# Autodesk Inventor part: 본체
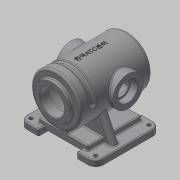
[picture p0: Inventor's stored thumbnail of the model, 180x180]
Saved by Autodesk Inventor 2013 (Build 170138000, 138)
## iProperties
Created: 2015-10
Part Number: 본체
Document SubType Name: Modeling
Designer: mdu
Density: 2.71 g/cm^3
Material: 일반
Mass: 4592.12 g
Surface Area: 2715.66 cm^2
Volume: 1694.51 cm^3
Author: mdu
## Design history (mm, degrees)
sketch "스케치1"
  geometry: L1 (-100, 85)-(-50, 85); L2 (-50, 85)-(-50, -85); L3 (-50, -85)-(-100, -85); L4 (-100, -85)-(-100, 85); L5 (50, 85)-(100, 85); L6 (100, 85)-(100, -85); L7 (100, -85)-(50, -85); L8 (50, -85)-(50, 85); 3 further points
  constraints: 16 end point, 4 parallel, 2 equal length, 2 horizontal, 2 horizontal alignment, 2 midpoint, 2 perpendicular
  dimensions: "d0" = 100 distance between parallel lines of L8 L2; "d1" = 170 distance of L3.end L1.start; "d3" = 200 distance between parallel lines of L6 L4; "d4" = 50 distance from line of point (0, 0) L2 (= 0.5 x d0)
extrude "돌출1" new body sketch "스케치1" distance "d5" = 16; taper "d6" = 0 deg
node "작업 평면1"
sketch "스케치2"
  geometry: L1 (-65, 70)-(65, 70); L2 (65, 70)-(65, -70); L3 (65, -70)-(-65, -70); L4 (-65, -70)-(-65, 70); 3 further points
  constraints: 8 end point, 2 midpoint, 2 parallel, 1 horizontal, 1 horizontal alignment, 1 perpendicular, 1 vertical alignment
  dimensions: "d8" = 130 distance of L2.end L3.end; "d9" = 140 distance of L1.end L2.end
extrude "돌출2" join sketch "스케치2" distance "d10" = 20; taper "d11" = 0 deg
sketch "스케치3"
  geometry: L1 (-100, 110)-(100, 110); L2 (85, 0)-(-85, 0) reference; L3 (100, 110)-(100, 175); L4 (100, 175)-(-90, 175); L5 (-90, 175)-(-90, 156); L6 (-90, 156)-(-100, 156); L7 (-100, 156)-(-100, 110); L8 (90, 110)-(90, 165); L9 (90, 165)-(-75, 165); L10 (-75, 165)-(-75, 110); L11 (-100, 142.5)-(-75, 142.5); 3 further points
  constraints: 20 end point, 5 perpendicular, 4 parallel, 4 point on line, 2 midpoint, 1 horizontal, 1 vertical alignment
  dimensions: "d12" = 110 distance from line of L2 L1.end; "d13" = 200 distance of L1.start L1.end; "d14" = 130 diameter of L4 L1; "d15" = 92 diameter of L6 L1; "d16" = 10 distance of L5.end L6.end; "d42" = 110 diameter of L9 L1; "d43" = 10 distance between parallel lines of L3 L8; "d44" = 25 distance between parallel lines of L10 L7; "d45" = 65 diameter of L11 L1
revolve "회전1" sketch "스케치3" stored, may be unused: angle "d17" = 90 deg
sketch "스케치4"
  geometry: L1 (-50, 70)-(50, 70) reference; L2 (50, -70)-(-50, -70) reference; L3 (-10, 70)-(-10, -70); L4 (10, -70)-(10, 70); 1 further point
  constraints: 4 end point, 4 point on line, 2 perpendicular
  dimensions: "d18" = 20 distance between parallel lines of L4 L3; "d19" = 10 distance from line of point (0, 0) L3
extrude "돌출3" join sketch "스케치4" stored distance "d20" = 10; taper "d21" = 0 deg
node "작업 평면2"
sketch "스케치5"
  geometry: L1 (-50, -8)-(0, -8) reference; L2 (100, -8)-(150, -8) reference; L3 (-40, -8)-(-8.943, -74.601); L4 (140, -8)-(108.943, -74.601); L5 (-50, 8)-(-50, -8) reference; L6 (150, 8)-(150, -8) reference; A1 r 65 centre (50, -102) between (-8.943, -74.601) and (108.943, -74.601) reference; 1 further point
  constraints: 4 end point, 2 point on circle, 2 point on line, 1 equal length
  dimensions: "d23" = 10 distance from line of L3.start L5; "d24" = 10 distance from line of L4.start L6; "d25" = 25 deg angle of L3 L5
feature "리브1" sketch "스케치5" dims "d26" = 1, "d27" = 20, "d28" = 0
node "작업 평면3"
sketch "스케치6"
  geometry: L1 (100, 156)-(100, 64) reference; C1 r 40 at (-25, 110); 2 further points
  constraints: 1 centre point, 1 horizontal alignment, 1 midpoint
  dimensions: "d37" = 80 diameter of C1; "d38" = 125 distance from line of C1.centre L1
extrude "돌출4" join sketch "스케치6" stored distance "d39" = 10; taper "d40" = 0 deg
hole "구멍1" diameter "d48" = 42; stored, may be unused: countersink angle "d52" = 90 deg, drill point angle "d54" = 118 deg; dims "d46" = 10, "d47" = 10, "d49" = 6, "d50" = 52, "d51" = 18, "d53" = 8
sketch "스케치7"
  geometry: C1 r 40 at (0, 0) reference; 2 further points
  constraints: 1 horizontal alignment
  dimensions: "d55" = 32.5 distance of point (32.5, 0) C1.centre
hole "구멍2" sketch "스케치7" at (32.5, 0) diameter "d56" = 3.242; stored, may be unused: countersink angle "d60" = 90 deg, drill point angle "d62" = 118 deg; dims "d57" = 11, "d58" = 52, "d59" = 18, "d61" = 13
sketch "스케치8"
  geometry: C1 r 46 at (0, 0) reference; 2 further points
  constraints: 1 vertical alignment
  dimensions: "d66" = 39 distance of C1.centre point (0, 39)
hole "구멍3" sketch "스케치8" at (0, 39) diameter "d67" = 3.242; stored, may be unused: countersink angle "d71" = 90 deg, drill point angle "d73" = 118 deg; dims "d68" = 11, "d69" = 52, "d70" = 18, "d72" = 13
fillet "모깎기7" dims "d77" = 20, "d78" = 5, "d79" = 3, "d80" = 10, "d107" = 10
fillet "모깎기8" dims "d81" = 3
fillet "모깎기9" dims "d82" = 3
fillet "모깎기10" dims "d83" = 3, "d84" = 0.3
chamfer "모따기1" distance "d85" = 1; stored, may be unused: second distance "d86" = 2, angle "d87" = 45 deg
node "작업 평면4"
sketch "스케치10"
  geometry: 5 further points
  constraints: 2 horizontal alignment, 2 vertical alignment
  dimensions: "d90" = 170 distance of point (85, 70) point (-85, 70); "d91" = 140 distance of point (-85, 70) point (-85, -70); "d92" = 70 vertical distance of point (0, 0) point (-85, -70) (= 0.5 x d91); "d93" = 85 horizontal distance of point (0, 0) point (-85, 70) (= 0.5 x d90)
hole "구멍4" sketch "스케치10" at (-85, 70), (85, 70), (85, -70), (-85, -70) diameter "d94" = 10; stored, may be unused: countersink angle "d98" = 90 deg, drill point angle "d100" = 118 deg; dims "d95" = 6, "d96" = 4, "d97" = 2, "d99" = 8
node "작업 평면5"
sketch "스케치12" dims "d22" = -90
  geometry: L1 (-65, -90)-(65, -90) reference; L2 (65, 85)-(-65, 85) reference; L3 (0, -90)-(0, 85); 3 further points
  constraints: 3 midpoint, 2 end point, 1 coincident, 1 other
feature "엠보싱3" sketch "스케치12" dims "d105" = 1, "d106" = 0
node "작업축1"
sketch "스케치13"
  geometry: L1 (-85, 175)-(90, 175) reference; L2 (-65, 175)-(-50, 175); L3 (-50, 175)-(-50, 170); L4 (-50, 170)-(-65, 170); L5 (-65, 170)-(-65, 175); L6 (-90, 50)-(-90, 170) reference; L7 (-140, 110)-(140, 110) reference; 1 further point
  constraints: 8 end point, 2 parallel, 1 horizontal, 1 perpendicular, 1 point on line
  dimensions: "d108" = 25 distance between parallel lines of L5 L6; "d109" = 15 distance of L3.end L4.end; "d110" = 5 distance of L2.end L3.end
revolve "회전2" sketch "스케치13" stored, may be unused: angle "d111" = 180 deg
fillet "모깎기11" dims "d112" = 5
fillet "모깎기12" dims "d113" = 5
fillet "모깎기13" dims "d114" = 3
node "솔리드1"
mirror "대칭1"
pattern_circular "원형 패턴1" dims angle "d64" = 360 deg
mirror "대칭3"
pattern_circular "원형 패턴2" dims angle "d75" = 360 deg
other parameters: "d7" = 8, "d36" = -75
